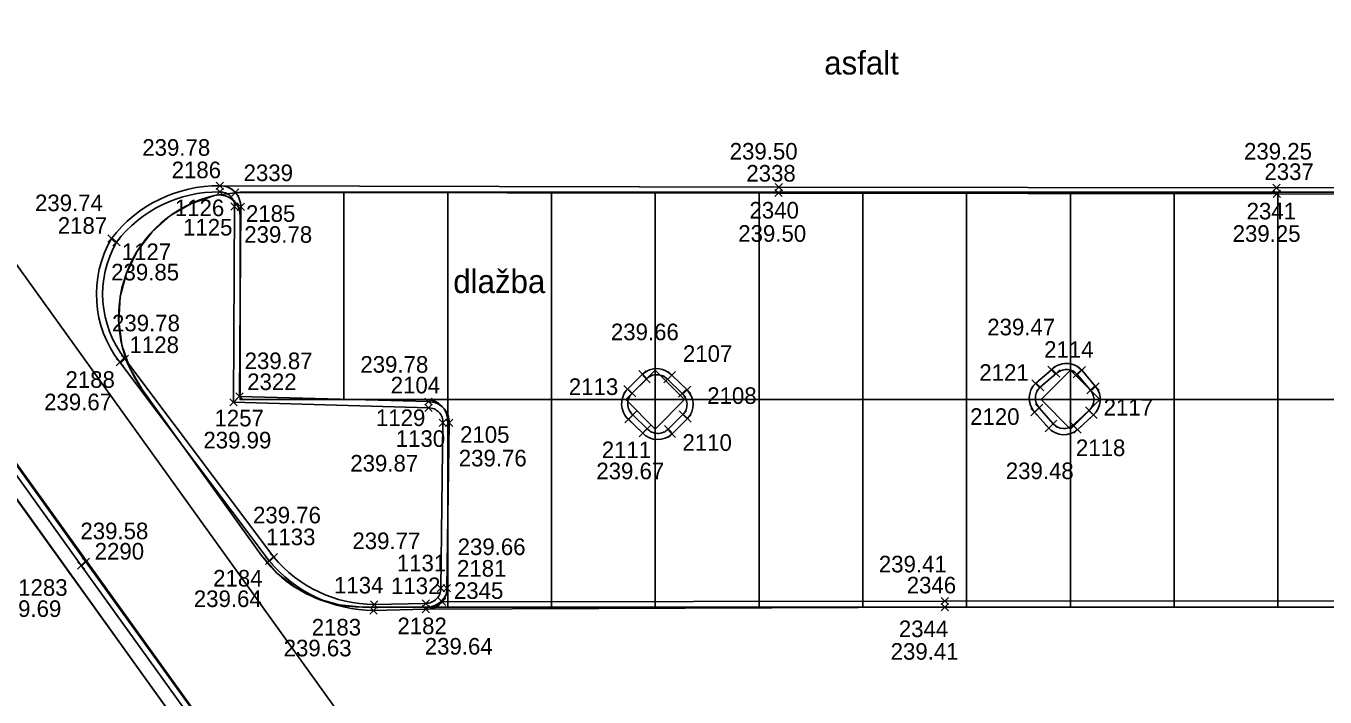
# Model space of a CAD drawing. Extents: x -264222 to -263676, y -1242344 to -1242060.
# Drawn here: x -264179.73 to -264148.43, y -1242230.65 to -1242214.48 of the extents above; entities that cross this region are included whole.
import ezdxf

# ---------------------------------------------------------------- set-up
doc = ezdxf.new("R2010")
doc.units = 0
for name, color, linetype in [('BODY_CISLO', 7, 'Continuous'), ('BODY_SYMBOL', 7, 'Continuous'), ('BODY_VYSKA', 7, 'Continuous'), ('KOORDINACNA_SITUACIA_DSP', 7, 'Continuous'), ('POPIS', 7, 'Continuous'), ('PROJEKT_DRS_OBRUBNIKY_KOMUNIKACIE', 7, 'Continuous'), ('PROJEKT_DRS_TDZ_VODOROVNE', 7, 'Continuous'), ('SO_20-3_OBRUBNIKY_DOLNA_HRANA', 7, 'Continuous'), ('SO_20-3_OBRUBNIKY_HORNA_HRANA', 7, 'Continuous')]:
    doc.layers.add(name, color=color, linetype=linetype)

msp = doc.modelspace()

# ---------------------------------------------------------------- linework, layer by layer
at = {"layer": 'BODY_SYMBOL'}
for p, q in [((-264175.146, -1242218.418), (-264174.97, -1242218.242)), ((-264174.97, -1242218.418), (-264175.146, -1242218.242)), ((-264161.682, -1242218.447), (-264161.506, -1242218.271)), ((-264161.506, -1242218.447), (-264161.682, -1242218.271)), ((-264149.687, -1242218.465), (-264149.511, -1242218.289)), ((-264149.511, -1242218.465), (-264149.687, -1242218.289)), ((-264175.148, -1242218.564), (-264174.972, -1242218.388)), ((-264174.972, -1242218.564), (-264175.148, -1242218.388)), ((-264174.771, -1242218.58), (-264174.595, -1242218.404)), ((-264174.595, -1242218.58), (-264174.771, -1242218.404)), ((-264161.687, -1242218.591), (-264161.511, -1242218.415)), ((-264161.511, -1242218.591), (-264161.687, -1242218.415)), ((-264149.685, -1242218.609), (-264149.509, -1242218.433)), ((-264149.509, -1242218.609), (-264149.685, -1242218.433)), ((-264174.788, -1242218.916), (-264174.612, -1242218.74)), ((-264174.612, -1242218.916), (-264174.788, -1242218.74)), ((-264174.641, -1242218.926), (-264174.465, -1242218.75)), ((-264174.465, -1242218.926), (-264174.641, -1242218.75)), ((-264177.758, -1242219.687), (-264177.582, -1242219.511)), ((-264177.582, -1242219.687), (-264177.758, -1242219.511)), ((-264177.634, -1242219.774), (-264177.458, -1242219.598)), ((-264177.458, -1242219.774), (-264177.634, -1242219.598)), ((-264177.557, -1242222.669), (-264177.381, -1242222.493)), ((-264177.381, -1242222.669), (-264177.557, -1242222.493)), ((-264177.434, -1242222.584), (-264177.258, -1242222.408)), ((-264177.258, -1242222.584), (-264177.434, -1242222.408)), ((-264155.114, -1242222.852), (-264154.938, -1242222.676)), ((-264154.938, -1242222.852), (-264155.114, -1242222.676)), ((-264154.383, -1242222.86), (-264154.207, -1242222.684)), ((-264154.207, -1242222.86), (-264154.383, -1242222.684)), ((-264164.959, -1242222.957), (-264164.783, -1242222.781)), ((-264164.783, -1242222.957), (-264164.959, -1242222.781)), ((-264164.869, -1242223.073), (-264164.693, -1242222.897)), ((-264164.693, -1242223.073), (-264164.869, -1242222.897)), ((-264164.36, -1242223.08), (-264164.184, -1242222.904)), ((-264164.184, -1242223.08), (-264164.36, -1242222.904)), ((-264164.257, -1242222.979), (-264164.081, -1242222.803)), ((-264164.081, -1242222.979), (-264164.257, -1242222.803)), ((-264155.496, -1242223.178), (-264155.32, -1242223.002)), ((-264155.32, -1242223.178), (-264155.496, -1242223.002)), ((-264154.998, -1242222.943), (-264154.822, -1242222.767)), ((-264154.822, -1242222.943), (-264154.998, -1242222.767)), ((-264154.497, -1242222.957), (-264154.321, -1242222.781)), ((-264154.321, -1242222.957), (-264154.497, -1242222.781)), ((-264174.669, -1242223.49), (-264174.493, -1242223.314)), ((-264174.493, -1242223.49), (-264174.669, -1242223.314)), ((-264165.322, -1242223.315), (-264165.146, -1242223.139)), ((-264165.146, -1242223.315), (-264165.322, -1242223.139)), ((-264165.213, -1242223.417), (-264165.037, -1242223.241)), ((-264165.037, -1242223.417), (-264165.213, -1242223.241)), ((-264164.007, -1242223.422), (-264163.831, -1242223.246)), ((-264163.831, -1242223.422), (-264164.007, -1242223.246)), ((-264163.889, -1242223.334), (-264163.713, -1242223.158)), ((-264163.713, -1242223.334), (-264163.889, -1242223.158)), ((-264155.385, -1242223.27), (-264155.209, -1242223.094)), ((-264155.209, -1242223.27), (-264155.385, -1242223.094)), ((-264154.17, -1242223.338), (-264153.994, -1242223.162)), ((-264153.994, -1242223.338), (-264154.17, -1242223.162)), ((-264154.049, -1242223.25), (-264153.873, -1242223.074)), ((-264153.873, -1242223.25), (-264154.049, -1242223.074)), ((-264174.817, -1242223.634), (-264174.641, -1242223.458)), ((-264174.641, -1242223.634), (-264174.817, -1242223.458)), ((-264170.12, -1242223.618), (-264169.944, -1242223.442)), ((-264169.944, -1242223.618), (-264170.12, -1242223.442)), ((-264170.12, -1242223.769), (-264169.944, -1242223.593)), ((-264169.944, -1242223.769), (-264170.12, -1242223.593)), ((-264155.405, -1242223.77), (-264155.229, -1242223.594)), ((-264155.229, -1242223.77), (-264155.405, -1242223.594)), ((-264169.769, -1242224.127), (-264169.593, -1242223.951)), ((-264169.593, -1242224.127), (-264169.769, -1242223.951)), ((-264169.619, -1242224.131), (-264169.443, -1242223.955)), ((-264169.443, -1242224.131), (-264169.619, -1242223.955)), ((-264165.303, -1242224.044), (-264165.127, -1242223.868)), ((-264165.127, -1242224.044), (-264165.303, -1242223.868)), ((-264165.197, -1242223.933), (-264165.021, -1242223.757)), ((-264165.021, -1242223.933), (-264165.197, -1242223.757)), ((-264163.988, -1242223.931), (-264163.812, -1242223.755)), ((-264163.812, -1242223.931), (-264163.988, -1242223.755)), ((-264163.879, -1242224.024), (-264163.703, -1242223.848)), ((-264163.703, -1242224.024), (-264163.879, -1242223.848)), ((-264155.517, -1242223.868), (-264155.341, -1242223.692)), ((-264155.341, -1242223.868), (-264155.517, -1242223.692)), ((-264154.207, -1242223.83), (-264154.031, -1242223.654)), ((-264154.031, -1242223.83), (-264154.207, -1242223.654)), ((-264154.102, -1242223.937), (-264153.926, -1242223.761)), ((-264153.926, -1242223.937), (-264154.102, -1242223.761)), ((-264164.958, -1242224.379), (-264164.782, -1242224.203)), ((-264164.782, -1242224.379), (-264164.958, -1242224.203)), ((-264164.851, -1242224.269), (-264164.675, -1242224.093)), ((-264164.675, -1242224.269), (-264164.851, -1242224.093)), ((-264164.344, -1242224.277), (-264164.168, -1242224.101)), ((-264164.168, -1242224.277), (-264164.344, -1242224.101)), ((-264164.252, -1242224.397), (-264164.076, -1242224.221)), ((-264164.076, -1242224.397), (-264164.252, -1242224.221)), ((-264155.172, -1242224.257), (-264154.996, -1242224.081)), ((-264154.996, -1242224.257), (-264155.172, -1242224.081)), ((-264155.067, -1242224.155), (-264154.891, -1242223.979)), ((-264154.891, -1242224.155), (-264155.067, -1242223.979)), ((-264154.585, -1242224.181), (-264154.409, -1242224.005)), ((-264154.409, -1242224.181), (-264154.585, -1242224.005)), ((-264154.485, -1242224.293), (-264154.309, -1242224.117)), ((-264154.309, -1242224.293), (-264154.485, -1242224.117)), ((-264178.486, -1242227.563), (-264178.31, -1242227.387)), ((-264178.31, -1242227.563), (-264178.486, -1242227.387)), ((-264178.369, -1242227.479), (-264178.193, -1242227.303)), ((-264178.193, -1242227.479), (-264178.369, -1242227.303)), ((-264173.953, -1242227.453), (-264173.777, -1242227.277)), ((-264173.777, -1242227.453), (-264173.953, -1242227.277)), ((-264173.842, -1242227.363), (-264173.666, -1242227.187)), ((-264173.666, -1242227.363), (-264173.842, -1242227.187)), ((-264169.821, -1242228.115), (-264169.645, -1242227.939)), ((-264169.645, -1242228.115), (-264169.821, -1242227.939)), ((-264169.674, -1242228.113), (-264169.498, -1242227.937)), ((-264169.498, -1242228.113), (-264169.674, -1242227.937)), ((-264171.429, -1242228.506), (-264171.253, -1242228.33)), ((-264171.253, -1242228.506), (-264171.429, -1242228.33)), ((-264170.182, -1242228.478), (-264170.006, -1242228.302)), ((-264170.006, -1242228.478), (-264170.182, -1242228.302)), ((-264169.788, -1242228.438), (-264169.612, -1242228.262)), ((-264169.612, -1242228.438), (-264169.788, -1242228.262)), ((-264157.679, -1242228.421), (-264157.503, -1242228.245)), ((-264157.503, -1242228.421), (-264157.679, -1242228.245)), ((-264171.444, -1242228.647), (-264171.268, -1242228.471)), ((-264171.268, -1242228.647), (-264171.444, -1242228.471)), ((-264170.179, -1242228.621), (-264170.003, -1242228.445)), ((-264170.003, -1242228.621), (-264170.179, -1242228.445)), ((-264157.679, -1242228.569), (-264157.503, -1242228.393)), ((-264157.503, -1242228.569), (-264157.679, -1242228.393))]:
    msp.add_line(p, q, dxfattribs=at)
at = {"layer": 'KOORDINACNA_SITUACIA_DSP'}
for p, q in [((-264204.694, -1242191.482), (-264122.859, -1242305.266)), ((-264204.078, -1242191.482), (-264122.243, -1242305.266)), ((-264181.951, -1242217.458), (-264153.34, -1242257.238)), ((-264176.93, -1242223.234), (-264174.054, -1242227.234)), ((-264169.568, -1242227.982), (-264169.568, -1242223.982)), ((-264171.618, -1242228.482), (-264170.068, -1242228.482))]:
    msp.add_line(p, q, dxfattribs=at)
for points in [[(-264204.694, -1242191.482), (-264137.78, -1242284.52), (-264125.581, -1242301.482)], [(-264170.068, -1242223.482), (-264174.568, -1242223.482), (-264174.568, -1242219.049)]]:
    msp.add_lwpolyline(points, dxfattribs=at)
for points in [[(-264163.861, -1242223.482), (-264164.568, -1242222.775), (-264165.275, -1242223.482), (-264164.568, -1242224.189)], [(-264153.861, -1242223.482), (-264154.568, -1242222.775), (-264155.275, -1242223.482), (-264154.568, -1242224.189)]]:
    msp.add_lwpolyline(points, close=True, dxfattribs=at)
for centre, radius, start, end in [((-264174.495, -1242221.482), 3, 103.2476, 215.724), ((-264175.068, -1242219.049), 0.5, 0, 103.2476), ((-264170.068, -1242223.982), 0.5, 0, 90), ((-264171.618, -1242225.482), 3, 215.724, 270), ((-264170.068, -1242227.982), 0.5, 270, 0)]:
    msp.add_arc(centre, radius, start, end, dxfattribs=at)
at = {"layer": 'PROJEKT_DRS_OBRUBNIKY_KOMUNIKACIE'}
for p, q in [((-264204.694, -1242191.482), (-264115.871, -1242314.982)), ((-264204.078, -1242191.482), (-264119.571, -1242308.982)), ((-264175.182, -1242218.562), (-264175.739, -1242218.752)), ((-264175.093, -1242218.549), (-264175.182, -1242218.562)), ((-264175.003, -1242218.553), (-264175.093, -1242218.549)), ((-264174.568, -1242218.482), (-264175.068, -1242218.549)), ((-264174.916, -1242218.573), (-264175.003, -1242218.553)), ((-264174.833, -1242218.608), (-264174.916, -1242218.573)), ((-264174.757, -1242218.657), (-264174.833, -1242218.608)), ((-264134.568, -1242218.482), (-264174.568, -1242218.482)), ((-264175.739, -1242218.752), (-264176.247, -1242219.047)), ((-264174.692, -1242218.719), (-264174.757, -1242218.657)), ((-264174.639, -1242218.791), (-264174.692, -1242218.719)), ((-264174.6, -1242218.872), (-264174.639, -1242218.791)), ((-264174.576, -1242218.959), (-264174.6, -1242218.872)), ((-264176.247, -1242219.047), (-264176.689, -1242219.436)), ((-264174.568, -1242219.049), (-264174.576, -1242218.959)), ((-264174.568, -1242223.482), (-264174.568, -1242219.049)), ((-264176.689, -1242219.436), (-264177.046, -1242219.903)), ((-264177.046, -1242219.903), (-264177.305, -1242220.431)), ((-264177.305, -1242220.431), (-264177.456, -1242220.999)), ((-264177.456, -1242220.999), (-264177.493, -1242221.586)), ((-264177.493, -1242221.586), (-264177.415, -1242222.169)), ((-264177.415, -1242222.169), (-264177.225, -1242222.725)), ((-264177.225, -1242222.725), (-264176.93, -1242223.234)), ((-264164.568, -1242222.775), (-264165.275, -1242223.482)), ((-264163.861, -1242223.482), (-264164.568, -1242222.775)), ((-264164.568, -1242222.775), (-264164.568, -1242224.189)), ((-264164.568, -1242224.189), (-264164.568, -1242222.775)), ((-264154.568, -1242222.775), (-264155.275, -1242223.482)), ((-264153.861, -1242223.482), (-264154.568, -1242222.775)), ((-264154.568, -1242222.775), (-264154.568, -1242224.189)), ((-264154.568, -1242224.189), (-264154.568, -1242222.775)), ((-264176.93, -1242223.234), (-264174.054, -1242227.234)), ((-264170.068, -1242223.482), (-264174.568, -1242223.482)), ((-264169.97, -1242223.492), (-264170.068, -1242223.482)), ((-264169.876, -1242223.52), (-264169.97, -1242223.492)), ((-264169.79, -1242223.567), (-264169.876, -1242223.52)), ((-264169.714, -1242223.629), (-264169.79, -1242223.567)), ((-264169.652, -1242223.704), (-264169.714, -1242223.629)), ((-264165.275, -1242223.482), (-264164.568, -1242224.189)), ((-264164.568, -1242224.189), (-264163.861, -1242223.482)), ((-264155.275, -1242223.482), (-264154.568, -1242224.189)), ((-264154.568, -1242224.189), (-264153.861, -1242223.482)), ((-264169.606, -1242223.791), (-264169.652, -1242223.704)), ((-264169.577, -1242223.885), (-264169.606, -1242223.791)), ((-264169.568, -1242223.982), (-264169.577, -1242223.885)), ((-264169.568, -1242227.982), (-264169.568, -1242223.982)), ((-264174.054, -1242227.234), (-264173.68, -1242227.661)), ((-264173.68, -1242227.661), (-264173.233, -1242228.011)), ((-264173.233, -1242228.011), (-264172.728, -1242228.269)), ((-264169.577, -1242228.08), (-264169.568, -1242227.982)), ((-264172.728, -1242228.269), (-264172.183, -1242228.429)), ((-264169.79, -1242228.398), (-264169.714, -1242228.336)), ((-264169.714, -1242228.336), (-264169.652, -1242228.26)), ((-264169.652, -1242228.26), (-264169.606, -1242228.174)), ((-264169.606, -1242228.174), (-264169.577, -1242228.08)), ((-264172.183, -1242228.429), (-264171.618, -1242228.482)), ((-264171.618, -1242228.482), (-264170.068, -1242228.482)), ((-264170.068, -1242228.482), (-264169.97, -1242228.473)), ((-264170.068, -1242228.482), (-264134.568, -1242228.482)), ((-264169.97, -1242228.473), (-264169.876, -1242228.444)), ((-264169.876, -1242228.444), (-264169.79, -1242228.398))]:
    msp.add_line(p, q, dxfattribs=at)
msp.add_lwpolyline([(-264204.694, -1242191.482), (-264137.78, -1242284.52), (-264125.581, -1242301.482)], dxfattribs=at)
at = {"layer": 'PROJEKT_DRS_TDZ_VODOROVNE'}
for p, q in [((-264172.068, -1242223.482), (-264172.068, -1242218.482)), ((-264169.568, -1242223.482), (-264169.568, -1242218.482)), ((-264167.068, -1242223.482), (-264167.068, -1242218.482)), ((-264164.568, -1242223.482), (-264164.568, -1242218.482)), ((-264162.068, -1242223.482), (-264162.068, -1242218.482)), ((-264159.568, -1242223.482), (-264159.568, -1242218.482)), ((-264157.068, -1242223.482), (-264157.068, -1242218.482)), ((-264154.568, -1242223.482), (-264154.568, -1242218.482)), ((-264152.068, -1242223.482), (-264152.068, -1242218.482)), ((-264149.568, -1242223.482), (-264149.568, -1242218.482)), ((-264134.568, -1242223.482), (-264174.568, -1242223.482)), ((-264169.568, -1242228.482), (-264169.568, -1242223.482)), ((-264167.068, -1242228.482), (-264167.068, -1242223.482)), ((-264164.568, -1242228.482), (-264164.568, -1242223.482)), ((-264162.068, -1242228.482), (-264162.068, -1242223.482)), ((-264159.568, -1242228.482), (-264159.568, -1242223.482)), ((-264157.068, -1242228.482), (-264157.068, -1242223.482)), ((-264154.568, -1242228.482), (-264154.568, -1242223.482)), ((-264152.068, -1242228.482), (-264152.068, -1242223.482)), ((-264149.568, -1242228.482), (-264149.568, -1242223.482))]:
    msp.add_line(p, q, dxfattribs=at)
at = {"layer": 'SO_20-3_OBRUBNIKY_DOLNA_HRANA'}
for p, q in [((-264173.865, -1242227.365), (-264177.469, -1242222.581)), ((-264164.871, -1242222.869), (-264165.234, -1242223.227)), ((-264164.169, -1242222.891), (-264163.801, -1242223.246)), ((-264155.408, -1242223.09), (-264155.026, -1242222.764)), ((-264154.295, -1242222.772), (-264153.961, -1242223.162)), ((-264164.87, -1242224.291), (-264165.215, -1242223.956)), ((-264163.791, -1242223.936), (-264164.164, -1242224.309)), ((-264155.084, -1242224.169), (-264155.429, -1242223.78)), ((-264154.014, -1242223.849), (-264154.397, -1242224.205)), ((-264169.531, -1242224.043), (-264169.586, -1242228.025)), ((-264171.356, -1242228.559), (-264170.091, -1242228.533))]:
    msp.add_line(p, q, dxfattribs=at)
for points in [[(-264179.08, -1242196.474), (-264200.47, -1242196.472), (-264195.765, -1242203.023), (-264189.923, -1242211.168), (-264184.11, -1242219.268), (-264178.281, -1242227.391), (-264171.252, -1242237.149), (-264164.83, -1242246.079), (-264158.406, -1242254.997), (-264151.981, -1242263.929), (-264145.549, -1242272.885), (-264139.496, -1242281.305), (-264132.148, -1242291.541), (-264125.165, -1242301.265), (-264124.808, -1242301.762)], [(-264134.113, -1242218.351), (-264149.599, -1242218.377), (-264161.594, -1242218.359), (-264175.058, -1242218.33)], [(-264174.683, -1242218.492), (-264161.599, -1242218.503), (-264149.597, -1242218.521), (-264134.479, -1242218.533)], [(-264174.553, -1242218.838), (-264174.581, -1242223.402), (-264170.032, -1242223.53)], [(-264169.7, -1242228.35), (-264157.591, -1242228.333), (-264146.598, -1242228.326), (-264134.446, -1242228.327)], [(-264134.12, -1242228.465), (-264146.604, -1242228.473), (-264157.591, -1242228.481), (-264170.091, -1242228.533)]]:
    msp.add_lwpolyline(points, dxfattribs=at)
for centre, major_axis, ratio, start_param, end_param in [((-264175.097, -1242221.569), (-3.235, -0.19), 0.999418, 4.64153, 5.570751), ((-264175.05, -1242218.827), (0.351, -0.353), 0.999799, 0.766822, 2.374771), ((-264175.342, -1242220.94), (-2.624, 0.578), 0.999702, 5.977213, 7.15726), ((-264164.531, -1242223.233), (-0.016, 0.498), 0.999633, 5.437792, 7.003305), ((-264154.664, -1242223.107), (-0.467, 0.174), 0.999602, 4.236346, 5.880759), ((-264164.865, -1242223.582), (0.013, -0.512), 0.999978, 3.920012, 5.504766), ((-264164.15, -1242223.596), (-0.288, 0.402), 0.999884, 3.333579, 4.878308), ((-264155.063, -1242223.446), (0.387, -0.309), 0.999802, 3.014173, 4.555504), ((-264154.342, -1242223.478), (0.067, 0.491), 0.999687, 4.00131, 5.53952), ((-264170.033, -1242224.032), (-0.439, -0.245), 0.999662, 2.611209, 4.201833), ((-264154.722, -1242223.832), (-0.023, -0.494), 0.999619, 5.507232, 7.046794), ((-264164.508, -1242223.943), (0.448, -0.226), 0.999453, 4.374652, 5.934929), ((-264171.333, -1242225.278), (3.132, -0.984), 0.99952, 4.135489, 5.009544), ((-264170.087, -1242228.032), (0.477, -0.155), 0.999793, 5.020254, 6.611437)]:
    msp.add_ellipse(centre, major_axis=major_axis, ratio=ratio, start_param=start_param, end_param=end_param, dxfattribs=at)
at = {"layer": 'SO_20-3_OBRUBNIKY_HORNA_HRANA'}
for p, q in [((-264177.346, -1242222.496), (-264173.754, -1242227.275)), ((-264165.125, -1242223.329), (-264164.781, -1242222.985)), ((-264164.272, -1242222.992), (-264163.919, -1242223.334)), ((-264155.297, -1242223.182), (-264154.91, -1242222.855)), ((-264154.409, -1242222.869), (-264154.082, -1242223.25)), ((-264164.763, -1242224.181), (-264165.109, -1242223.845)), ((-264163.9, -1242223.843), (-264164.256, -1242224.189)), ((-264154.979, -1242224.067), (-264155.317, -1242223.682)), ((-264154.119, -1242223.742), (-264154.497, -1242224.093)), ((-264169.733, -1242228.027), (-264169.681, -1242224.039)), ((-264171.341, -1242228.418), (-264170.094, -1242228.39))]:
    msp.add_line(p, q, dxfattribs=at)
for points in [[(-264204.226, -1242191.388), (-264204.22, -1242191.499), (-264200.55, -1242196.62), (-264195.884, -1242203.112), (-264190.046, -1242211.249), (-264184.226, -1242219.352), (-264178.398, -1242227.475), (-264171.378, -1242237.231), (-264164.951, -1242246.159), (-264158.525, -1242255.075), (-264152.106, -1242264.005), (-264145.671, -1242272.964), (-264139.631, -1242281.361), (-264132.272, -1242291.613), (-264125.285, -1242301.347), (-264124.926, -1242301.846)], [(-264170.032, -1242223.681), (-264174.729, -1242223.546), (-264174.7, -1242218.828)]]:
    msp.add_lwpolyline(points, dxfattribs=at)
for centre, major_axis, ratio, start_param, end_param in [((-264175.086, -1242221.579), (-3.104, -0.089), 0.999443, 4.675385, 5.598376), ((-264175.045, -1242218.821), (0.291, -0.185), 0.999814, 0.546101, 2.18113), ((-264175.352, -1242220.942), (-2.522, 0.171), 0.999676, 5.830858, 7.013208), ((-264164.53, -1242223.233), (-0.245, -0.254), 0.999287, 3.090815, 4.70239), ((-264154.666, -1242223.099), (-0.259, -0.227), 0.999033, 3.149842, 4.77799), ((-264164.877, -1242223.579), (-0.049, -0.35), 0.998366, 4.062287, 5.703068), ((-264164.159, -1242223.598), (0.059, 0.352), 0.999813, 4.122485, 5.71135), ((-264155.058, -1242223.442), (-0.196, 0.294), 0.999303, 0.154553, 1.728117), ((-264154.356, -1242223.477), (0.063, 0.351), 0.999205, 4.049054, 5.579469), ((-264170.026, -1242224.025), (-0.331, 0.097), 0.997604, 3.387013, 5.013937), ((-264164.506, -1242223.947), (0.345, -0.048), 0.997959, 4.020973, 5.651512), ((-264154.726, -1242223.841), (0.231, -0.249), 0.997432, 4.69232, 6.272976), ((-264171.322, -1242225.259), (3.001, -0.989), 0.999776, 4.152132, 5.024521), ((-264170.094, -1242228.029), (0.004, 0.361), 0.999749, 3.151838, 4.730405)]:
    msp.add_ellipse(centre, major_axis=major_axis, ratio=ratio, start_param=start_param, end_param=end_param, dxfattribs=at)

# ---------------------------------------------------------------- texts
at = {"layer": 'BODY_CISLO'}
for s, p in [('2186', (-264176.217, -1242218.147)), ('2339', (-264174.484, -1242218.216)), ('2338', (-264162.374, -1242218.228)), ('2337', (-264149.893, -1242218.189)), ('1126', (-264176.14, -1242219.061)), ('2185', (-264174.427, -1242219.198)), ('2340', (-264162.297, -1242219.118)), ('2341', (-264150.322, -1242219.139)), ('2187', (-264178.96, -1242219.486)), ('1125', (-264175.943, -1242219.528)), ('1127', (-264177.42, -1242220.119)), ('1128', (-264177.231, -1242222.358)), ('2114', (-264155.199, -1242222.473)), ('2107', (-264163.901, -1242222.572)), ('2121', (-264156.761, -1242223.028)), ('2188', (-264178.775, -1242223.197)), ('2322', (-264174.397, -1242223.251)), ('2104', (-264170.94, -1242223.331)), ('2113', (-264166.649, -1242223.369)), ('2108', (-264163.315, -1242223.585)), ('2117', (-264153.767, -1242223.865)), ('1257', (-264175.185, -1242224.126)), ('1129', (-264171.296, -1242224.117)), ('2120', (-264156.982, -1242224.09)), ('1130', (-264170.819, -1242224.62)), ('2105', (-264169.269, -1242224.521)), ('2111', (-264165.856, -1242224.891)), ('2110', (-264163.912, -1242224.714)), ('2118', (-264154.434, -1242224.841)), ('1133', (-264173.943, -1242226.988)), ('2290', (-264178.071, -1242227.334)), ('1131', (-264170.793, -1242227.618)), ('2181', (-264169.343, -1242227.746)), ('2184', (-264175.218, -1242227.984)), ('1283', (-264179.914, -1242228.208)), ('1134', (-264172.306, -1242228.152)), ('1132', (-264170.933, -1242228.167)), ('2345', (-264169.417, -1242228.282)), ('2346', (-264158.509, -1242228.149)), ('2183', (-264172.843, -1242229.164)), ('2182', (-264170.778, -1242229.133)), ('2344', (-264158.699, -1242229.203))]:
    msp.add_text(s, height=0.4, dxfattribs=at).set_placement(p)
at = {"layer": 'BODY_VYSKA'}
for s, p in [('239.78', (-264176.924, -1242217.606)), ('239.50', (-264162.774, -1242217.698)), ('239.25', (-264150.384, -1242217.698)), ('239.74', (-264179.509, -1242218.94)), ('239.78', (-264174.468, -1242219.702)), ('239.50', (-264162.568, -1242219.678)), ('239.25', (-264150.659, -1242219.68)), ('239.85', (-264177.674, -1242220.609)), ('239.78', (-264177.654, -1242221.835)), ('239.66', (-264165.636, -1242222.05)), ('239.47', (-264156.57, -1242221.932)), ('239.87', (-264174.459, -1242222.746)), ('239.78', (-264171.671, -1242222.832)), ('239.67', (-264179.289, -1242223.738)), ('239.99', (-264175.452, -1242224.656)), ('239.87', (-264171.914, -1242225.214)), ('239.76', (-264169.3, -1242225.09)), ('239.67', (-264165.987, -1242225.4)), ('239.48', (-264156.123, -1242225.396)), ('239.76', (-264174.257, -1242226.462)), ('239.58', (-264178.415, -1242226.845)), ('239.77', (-264171.863, -1242227.083)), ('239.66', (-264169.328, -1242227.226)), ('239.41', (-264159.181, -1242227.644)), ('239.69', (-264180.511, -1242228.717)), ('239.64', (-264175.683, -1242228.478)), ('239.63', (-264173.519, -1242229.666)), ('239.64', (-264170.12, -1242229.624)), ('239.41', (-264158.897, -1242229.748))]:
    msp.add_text(s, height=0.4, dxfattribs=at).set_placement(p)
at = {"layer": 'POPIS'}
msp.add_text('asfalt', height=0.5625, dxfattribs=at).set_placement((-264160.497, -1242215.648))
msp.add_text('dlažba', height=0.5625, rotation=360, dxfattribs=at).set_placement((-264169.433, -1242220.914))

doc.saveas('drawing.dxf')
